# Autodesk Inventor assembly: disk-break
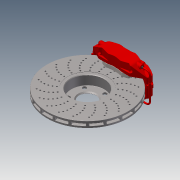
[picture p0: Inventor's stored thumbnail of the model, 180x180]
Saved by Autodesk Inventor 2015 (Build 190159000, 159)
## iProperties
Created: 2015-04
Part Number: disk-break
Document SubType Name: Assembly
Designer: Gabriel Cabellos
Sending System: SolidWorks 2011
Last Author: Pets
Author: Gabriel Cabellos
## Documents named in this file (11)
- C:\Users\Renato\Documents\Guilherme de Souza Dias\WS2015 CAD Data ANLAS\#33- Automobile Technology\disk-brake\disk-break.iam
- C:\Users\Renato\Desktop\Outros\OC2015\Imported Components\Disk brake\Caliper part3.ipt
- C:\Users\Renato\Desktop\Outros\OC2015\Imported Components\Disk brake\Caliper part2.ipt
- C:\Users\Renato\Desktop\Outros\OC2015\Imported Components\Disk brake\Disk brake.ipt
- C:\Users\Renato\Desktop\Outros\OC2015\Imported Components\Disk brake\Brake pad.ipt
- C:\Users\Renato\Desktop\Outros\OC2015\Imported Components\Disk brake\Bolt.ipt
- C:\Users\Renato\Desktop\Outros\OC2015\Imported Components\Disk brake\Pipe.ipt
- C:\Users\Renato\Desktop\Outros\OC2015\Imported Components\Disk brake\Nut.ipt
- C:\Users\Renato\Desktop\Outros\OC2015\Imported Components\Disk brake\Rod1.ipt
- C:\Users\Renato\Desktop\Outros\OC2015\Imported Components\Disk brake\Rod bolt.ipt
- C:\Users\Renato\Desktop\Outros\OC2015\Imported Components\Disk brake\Rod2.ipt
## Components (18 placed, 10 different names)
1. Caliper part3:2
2. Caliper part2:1
3. Disk brake:1
4. Brake pad:1
5. Brake pad:2
6. Bolt:1
7. Bolt:2
8. Bolt:3
9. Bolt:4
10. Pipe:1
11. Nut:1
12. Nut:2
13. Nut:3
14. Nut:4
15. Rod1:1
16. Rod bolt:1
17. Rod2:1
18. Rod2:2
